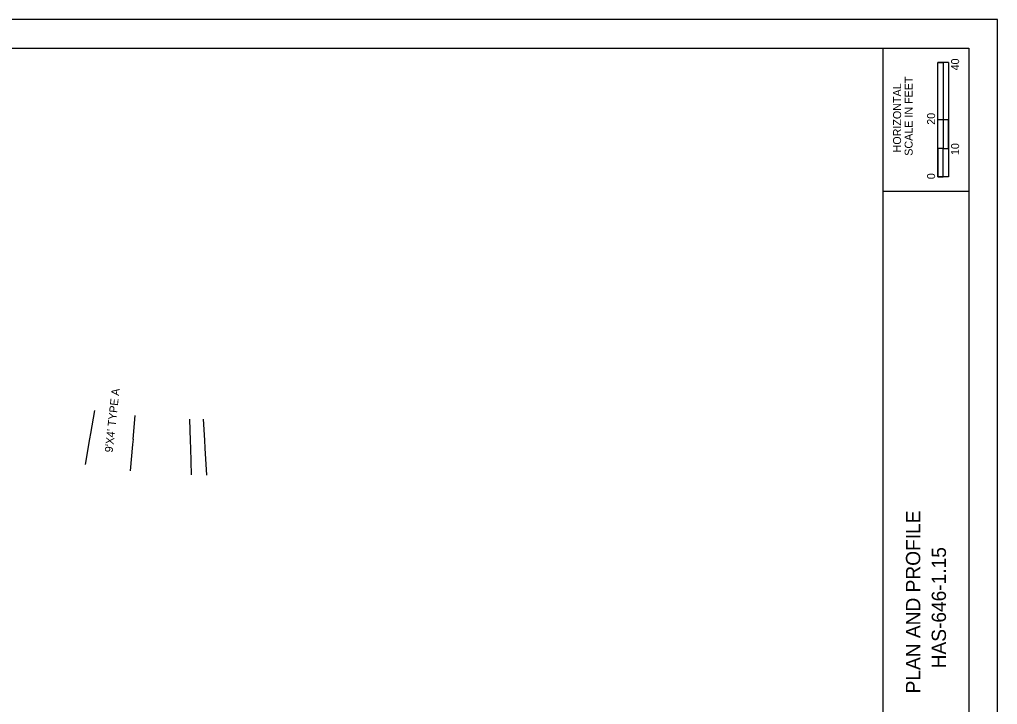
# Model space of a CAD drawing. Extents: x -0.2 to 34, y 0 to 22.
# Drawn here: x 16.9 to 34, y 10.03 to 22 of the extents above; entities that cross this region are included whole.
import ezdxf

# ---------------------------------------------------------------- set-up
doc = ezdxf.new("R2010")
doc.units = 0
for name, color, linetype in [('SH_Border', 7, 'Continuous'), ('SH_Cut_Line', 7, 'Continuous'), ('SH_Data', 7, 'Continuous'), ('SH_Text', 7, 'Continuous')]:
    doc.layers.add(name, color=color, linetype=linetype)

msp = doc.modelspace()

# ---------------------------------------------------------------- linework, layer by layer
at = {"layer": 'SH_Border'}
for p, q in [((32, 0.5), (32, 21.5)), ((32, 19), (33.5, 19))]:
    msp.add_line(p, q, dxfattribs=at)
msp.add_lwpolyline([(1.5, 21.5), (33.5, 21.5), (33.5, 0.5), (1.5, 0.5)], close=True, dxfattribs=at)
at = {"layer": 'SH_Cut_Line'}
msp.add_lwpolyline([(0, 0), (34, 0), (34, 22), (0, 22)], close=True, dxfattribs=at)
at = {"layer": 'SH_Data'}
for p, q in [((32.957, 19.25), (32.957, 21.25)), ((33.144, 21.25), (32.957, 21.25)), ((32.957, 20.25), (32.957, 21.25)), ((32.957, 21.25), (33.05, 21.25)), ((33.05, 21.25), (33.051, 21.25)), ((33.051, 21.25), (33.051, 20.25)), ((33.144, 21.25), (33.144, 19.25)), ((33.051, 20.25), (32.957, 20.25)), ((33.143, 20.25), (33.05, 20.25)), ((33.05, 20.25), (33.05, 19.75)), ((33.143, 19.75), (33.143, 20.25)), ((33.05, 19.75), (32.957, 19.75)), ((32.957, 19.75), (32.957, 19.25)), ((33.05, 19.25), (33.05, 19.75)), ((33.05, 19.75), (33.143, 19.75)), ((33.144, 19.25), (32.957, 19.25)), ((32.957, 19.25), (33.05, 19.25))]:
    msp.add_line(p, q, dxfattribs=at)
at = {"layer": 'SH_Text'}
for p, q in [((18.212, 15.172), (18.141, 14.768)), ((18.884, 14.67), (18.92, 15.081)), ((19.873, 15.021), (19.883, 14.64)), ((20.113, 15.017), (20.133, 14.65)), ((18.141, 14.768), (18.125, 14.674)), ((18.125, 14.674), (18.046, 14.225)), ((18.876, 14.577), (18.836, 14.118)), ((18.884, 14.67), (18.876, 14.577)), ((19.883, 14.64), (19.887, 14.514)), ((20.133, 14.65), (20.141, 14.51)), ((19.887, 14.514), (19.899, 14.044)), ((20.141, 14.51), (20.167, 14.039))]:
    msp.add_line(p, q, dxfattribs=at)

# ---------------------------------------------------------------- texts
at = {"layer": 'SH_Data'}
for s, height, p in [('40', 0.14, (33.33, 21.112)), ('HORIZONTAL', 0.14, (32.315, 19.679)), ('SCALE IN FEET', 0.14, (32.517, 19.621)), ('20', 0.14, (32.91, 20.162)), ('10', 0.14, (33.33, 19.633)), ('0', 0.14, (32.91, 19.211)), ('PLAN AND PROFILE', 0.25, (32.65, 10.227)), ('HAS-646-1.15', 0.25, (33.1, 10.665))]:
    msp.add_text(s, height=height, rotation=90, dxfattribs=at).set_placement(p)
at = {"layer": 'SH_Text'}
msp.add_text("9'X4' TYPE A", height=0.14, rotation=83.6556, dxfattribs=at).set_placement((18.527, 14.432))

doc.saveas('drawing.dxf')
